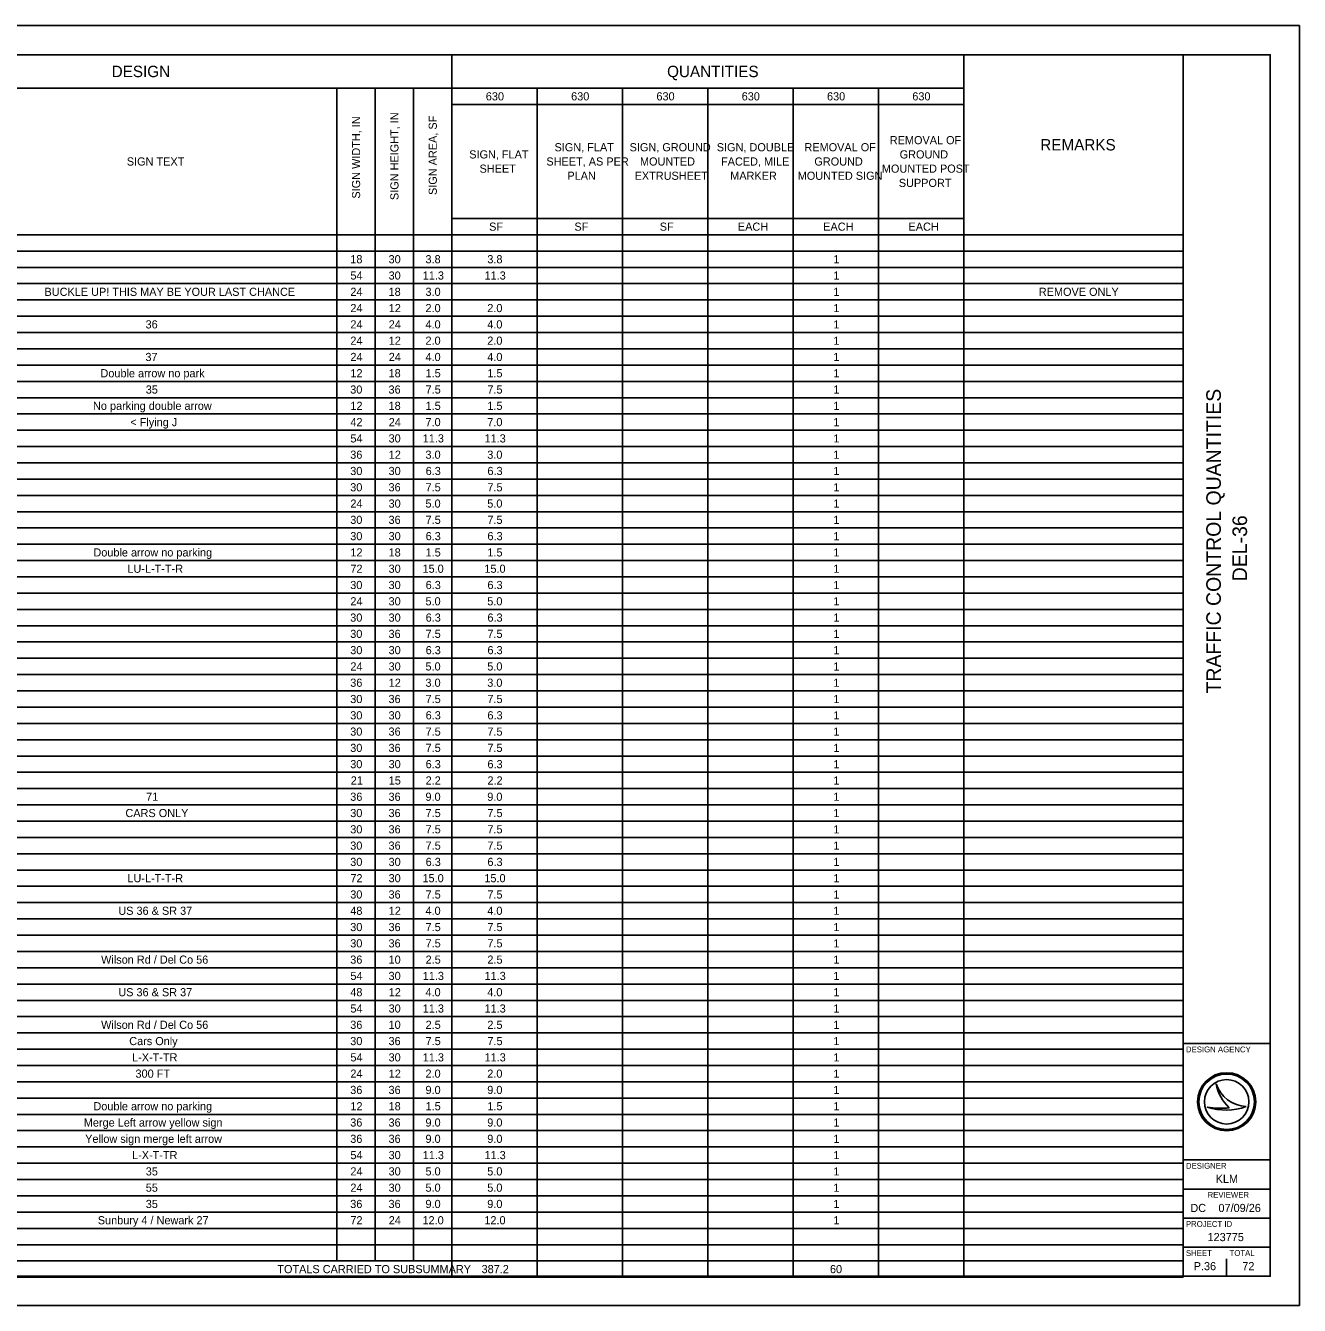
# Model space of a CAD drawing. Extents: x 0 to 34, y 0 to 22.
# Drawn here: x 12.11 to 34, y 0 to 22 of the extents above; entities that cross this region are included whole.
import ezdxf

# ---------------------------------------------------------------- set-up
doc = ezdxf.new("R2010")
doc.units = 0
for name, color, linetype in [('SH_Border', 7, 'Continuous'), ('SH_Cut_Line', 7, 'Continuous'), ('SH_Data', 7, 'Continuous'), ('SH_Text', 7, 'Continuous')]:
    doc.layers.add(name, color=color, linetype=linetype)

msp = doc.modelspace()

# ---------------------------------------------------------------- linework, layer by layer
at = {"layer": 'SH_Border'}
for p, q in [((32, 0.5), (32, 21.5)), ((32, 4.5), (33.5, 4.5)), ((32, 2.5), (33.5, 2.5)), ((32, 2), (33.5, 2)), ((32, 1.5), (33.5, 1.5)), ((32, 1), (33.5, 1))]:
    msp.add_line(p, q, dxfattribs=at)
msp.add_lwpolyline([(1.5, 21.5), (33.5, 21.5), (33.5, 0.5), (1.5, 0.5)], close=True, dxfattribs=at)
at = {"layer": 'SH_Cut_Line'}
msp.add_lwpolyline([(0, 0), (34, 0), (34, 22), (0, 22)], close=True, dxfattribs=at)
at = {"layer": 'SH_Data'}
for p, q in [((1.5, 21.5), (32.004, 21.5)), ((19.436, 21.5), (19.436, 0.484)), ((28.232, 21.5), (28.232, 0.484)), ((32.004, 21.5), (32.004, 0.484)), ((1.5, 20.924), (28.232, 20.924)), ((17.46, 20.924), (17.46, 0.764)), ((18.119, 20.924), (18.119, 0.764)), ((18.778, 20.924), (18.778, 0.764)), ((20.902, 20.924), (20.902, 0.484)), ((22.368, 20.924), (22.368, 0.484)), ((23.834, 20.924), (23.834, 0.484)), ((25.3, 20.924), (25.3, 0.484)), ((26.766, 20.924), (26.766, 0.484)), ((19.436, 20.644), (28.232, 20.644)), ((19.436, 18.684), (28.232, 18.684)), ((1.5, 18.404), (32.004, 18.404)), ((1.5, 18.124), (32.004, 18.124)), ((1.5, 17.844), (32.004, 17.844)), ((1.5, 17.564), (32.004, 17.564)), ((1.5, 17.284), (32.004, 17.284)), ((1.5, 17.004), (32.004, 17.004)), ((1.5, 16.724), (32.004, 16.724)), ((1.5, 16.444), (32.004, 16.444)), ((1.5, 16.164), (32.004, 16.164)), ((1.5, 15.884), (32.004, 15.884)), ((1.5, 15.604), (32.004, 15.604)), ((1.5, 15.324), (32.004, 15.324)), ((1.5, 15.044), (32.004, 15.044)), ((1.5, 14.764), (32.004, 14.764)), ((1.5, 14.484), (32.004, 14.484)), ((1.5, 14.204), (32.004, 14.204)), ((1.5, 13.924), (32.004, 13.924)), ((1.5, 13.644), (32.004, 13.644)), ((1.5, 13.364), (32.004, 13.364)), ((1.5, 13.084), (32.004, 13.084)), ((1.5, 12.804), (32.004, 12.804)), ((1.5, 12.524), (32.004, 12.524)), ((1.5, 12.244), (32.004, 12.244)), ((1.5, 11.964), (32.004, 11.964)), ((1.5, 11.684), (32.004, 11.684)), ((1.5, 11.404), (32.004, 11.404)), ((1.5, 11.124), (32.004, 11.124)), ((1.5, 10.844), (32.004, 10.844)), ((1.5, 10.564), (32.004, 10.564)), ((1.5, 10.284), (32.004, 10.284)), ((1.5, 10.004), (32.004, 10.004)), ((1.5, 9.724), (32.004, 9.724)), ((1.5, 9.444), (32.004, 9.444)), ((1.5, 9.164), (32.004, 9.164)), ((1.5, 8.884), (32.004, 8.884)), ((1.5, 8.604), (32.004, 8.604)), ((1.5, 8.324), (32.004, 8.324)), ((1.5, 8.044), (32.004, 8.044)), ((1.5, 7.764), (32.004, 7.764)), ((1.5, 7.484), (32.004, 7.484)), ((1.5, 7.204), (32.004, 7.204)), ((1.5, 6.924), (32.004, 6.924)), ((1.5, 6.644), (32.004, 6.644)), ((1.5, 6.364), (32.004, 6.364)), ((1.5, 6.084), (32.004, 6.084)), ((1.5, 5.804), (32.004, 5.804)), ((1.5, 5.524), (32.004, 5.524)), ((1.5, 5.244), (32.004, 5.244)), ((1.5, 4.964), (32.004, 4.964)), ((1.5, 4.684), (32.004, 4.684)), ((1.5, 4.404), (32.004, 4.404)), ((1.5, 4.124), (32.004, 4.124)), ((1.5, 3.844), (32.004, 3.844)), ((32.567, 3.81), (32.567, 3.81)), ((1.5, 3.564), (32.004, 3.564)), ((32.417, 3.41), (32.417, 3.41)), ((32.75, 3.5), (32.75, 3.5)), ((33.087, 3.419), (33.087, 3.419)), ((1.5, 3.284), (32.004, 3.284)), ((1.5, 3.004), (32.004, 3.004)), ((1.5, 2.724), (32.004, 2.724)), ((1.5, 2.444), (32.004, 2.444)), ((1.5, 2.164), (32.004, 2.164)), ((1.5, 1.884), (32.004, 1.884)), ((1.5, 1.604), (32.004, 1.604)), ((1.5, 1.324), (32.004, 1.324)), ((1.5, 1.044), (32.004, 1.044)), ((1.5, 0.764), (32.004, 0.764)), ((32.375, 0.675), (32.375, 0.675)), ((32.75, 0.5), (32.75, 0.8)), ((1.5, 0.484), (32.004, 0.484))]:
    msp.add_line(p, q, dxfattribs=at)
for radius in [0.5, 0.477, 0.477, 0.382]:
    msp.add_circle((32.75, 3.5), radius, dxfattribs=at)
for centre, radius, start, end in [((33.116, 3.998), 0.58, 198.9257, 198.9319), ((33.347, 3.97), 0.796, 191.6379, 191.6421), ((33.116, 3.998), 0.58, 198.9319, 267.1657), ((33.347, 3.97), 0.796, 191.6421, 226.0947), ((32.739, 4.37), 1.013, 251.4576, 290.0832), ((32.648, 4.654), 1.266, 259.4964, 259.4995), ((32.739, 4.37), 1.013, 251.4527, 251.4576), ((32.648, 4.654), 1.266, 259.4995, 276.6672)]:
    msp.add_arc(centre, radius, start, end, dxfattribs=at)

# ---------------------------------------------------------------- texts
for s, p in [('TRAFFIC CONTROL QUANTITIES', (32.65, 10.519)), ('DEL-36', (33.1, 12.448))]:
    msp.add_text(s, height=0.25, rotation=90, dxfattribs=at).set_placement(p)
for s, height, p in [('DESIGN AGENCY', 0.1, (32.05, 4.35)), ('DESIGNER', 0.1, (32.05, 2.35)), ('KLM', 0.14, (32.561, 2.105)), ('REVIEWER', 0.1, (32.422, 1.85)), ('DC', 0.14, (32.126, 1.605)), ('07/09/26', 0.14, (32.609, 1.605)), ('PROJECT ID', 0.1, (32.05, 1.35)), ('123775', 0.14, (32.421, 1.105)), ('SHEET', 0.1, (32.05, 0.85)), ('TOTAL', 0.1, (32.8, 0.85)), ('P.36', 0.14, (32.183, 0.605)), ('72', 0.14, (33.019, 0.605))]:
    msp.add_text(s, height=height, dxfattribs=at).set_placement(p)
at = {"layer": 'SH_Text'}
for s, height, p in [('DESIGN', 0.196, (13.589, 21.114)), ('QUANTITIES', 0.196, (23.134, 21.114)), ('630', 0.14, (20.019, 20.714)), ('630', 0.14, (21.485, 20.714)), ('630', 0.14, (22.951, 20.714)), ('630', 0.14, (24.416, 20.714)), ('630', 0.14, (25.882, 20.714)), ('630', 0.14, (27.348, 20.714)), ('REMOVAL OF ', 0.14, (26.961, 19.961)), ('REMARKS', 0.196, (29.547, 19.854)), ('SIGN, FLAT ', 0.14, (19.734, 19.716)), ('SIGN, FLAT ', 0.14, (21.2, 19.839)), ('SIGN, GROUND ', 0.14, (22.49, 19.839)), ('SIGN, DOUBLE ', 0.14, (23.988, 19.839)), ('REMOVAL OF ', 0.14, (25.495, 19.839)), ('GROUND ', 0.14, (27.131, 19.716)), ('SIGN TEXT', 0.14, (13.85, 19.594)), ('SHEET', 0.14, (19.911, 19.471)), ('SHEET, AS PER ', 0.14, (21.06, 19.594)), ('MOUNTED ', 0.14, (22.668, 19.594)), ('FACED, MILE ', 0.14, (24.061, 19.594)), ('GROUND ', 0.14, (25.665, 19.594)), ('MOUNTED POST ', 0.14, (26.825, 19.471)), ('PLAN', 0.14, (21.421, 19.349)), ('EXTRUSHEET', 0.14, (22.576, 19.349)), ('MARKER', 0.14, (24.219, 19.349)), ('MOUNTED SIGN', 0.14, (25.379, 19.349)), ('SUPPORT', 0.14, (27.116, 19.226)), ('SF', 0.14, (20.076, 18.474)), ('SF', 0.14, (21.542, 18.474)), ('SF', 0.14, (23.008, 18.474)), ('EACH', 0.14, (24.351, 18.474)), ('EACH', 0.14, (25.817, 18.474)), ('EACH', 0.14, (27.283, 18.474)), ('18', 0.14, (17.69, 17.914)), ('30', 0.14, (18.348, 17.914)), ('3.8', 0.14, (18.982, 17.914)), ('3.8', 0.14, (20.045, 17.914)), ('1', 0.14, (25.992, 17.914)), ('54', 0.14, (17.692, 17.634)), ('30', 0.14, (18.348, 17.634)), ('11.3', 0.14, (18.935, 17.634)), ('11.3', 0.14, (19.997, 17.634)), ('1', 0.14, (25.992, 17.634)), ('BUCKLE UP! THIS MAY BE YOUR LAST CHANCE', 0.14, (12.435, 17.354)), ('24', 0.14, (17.692, 17.354)), ('18', 0.14, (18.348, 17.354)), ('3.0', 0.14, (18.982, 17.354)), ('1', 0.14, (25.992, 17.354)), ('REMOVE ONLY', 0.14, (29.522, 17.354)), ('24', 0.14, (17.692, 17.074)), ('12', 0.14, (18.351, 17.074)), ('2.0', 0.14, (18.982, 17.074)), ('2.0', 0.14, (20.044, 17.074)), ('1', 0.14, (25.992, 17.074)), ('36', 0.14, (14.172, 16.794)), ('24', 0.14, (17.692, 16.794)), ('24', 0.14, (18.351, 16.794)), ('4.0', 0.14, (18.982, 16.794)), ('4.0', 0.14, (20.044, 16.794)), ('1', 0.14, (25.992, 16.794)), ('24', 0.14, (17.692, 16.514)), ('12', 0.14, (18.351, 16.514)), ('2.0', 0.14, (18.982, 16.514)), ('2.0', 0.14, (20.044, 16.514)), ('1', 0.14, (25.992, 16.514)), ('37', 0.14, (14.169, 16.234)), ('24', 0.14, (17.692, 16.234)), ('24', 0.14, (18.351, 16.234)), ('4.0', 0.14, (18.982, 16.234)), ('4.0', 0.14, (20.044, 16.234)), ('1', 0.14, (25.992, 16.234)), ('Double arrow no park', 0.14, (13.397, 15.954)), ('12', 0.14, (17.692, 15.954)), ('18', 0.14, (18.348, 15.954)), ('1.5', 0.14, (18.984, 15.954)), ('1.5', 0.14, (20.046, 15.954)), ('1', 0.14, (25.992, 15.954)), ('35', 0.14, (14.175, 15.674)), ('30', 0.14, (17.689, 15.674)), ('36', 0.14, (18.347, 15.674)), ('7.5', 0.14, (18.984, 15.674)), ('7.5', 0.14, (20.046, 15.674)), ('1', 0.14, (25.992, 15.674)), ('No parking double arrow', 0.14, (13.269, 15.394)), ('12', 0.14, (17.692, 15.394)), ('18', 0.14, (18.348, 15.394)), ('1.5', 0.14, (18.984, 15.394)), ('1.5', 0.14, (20.046, 15.394)), ('1', 0.14, (25.992, 15.394)), ('< Flying J', 0.14, (13.91, 15.114)), ('42', 0.14, (17.692, 15.114)), ('24', 0.14, (18.351, 15.114)), ('7.0', 0.14, (18.982, 15.114)), ('7.0', 0.14, (20.044, 15.114)), ('1', 0.14, (25.992, 15.114)), ('54', 0.14, (17.692, 14.834)), ('30', 0.14, (18.348, 14.834)), ('11.3', 0.14, (18.935, 14.834)), ('11.3', 0.14, (19.997, 14.834)), ('1', 0.14, (25.992, 14.834)), ('36', 0.14, (17.689, 14.554)), ('12', 0.14, (18.351, 14.554)), ('3.0', 0.14, (18.982, 14.554)), ('3.0', 0.14, (20.044, 14.554)), ('1', 0.14, (25.992, 14.554)), ('30', 0.14, (17.689, 14.274)), ('30', 0.14, (18.348, 14.274)), ('6.3', 0.14, (18.985, 14.274)), ('6.3', 0.14, (20.047, 14.274)), ('1', 0.14, (25.992, 14.274)), ('30', 0.14, (17.689, 13.994)), ('36', 0.14, (18.347, 13.994)), ('7.5', 0.14, (18.984, 13.994)), ('7.5', 0.14, (20.046, 13.994)), ('1', 0.14, (25.992, 13.994)), ('24', 0.14, (17.692, 13.714)), ('30', 0.14, (18.348, 13.714)), ('5.0', 0.14, (18.982, 13.714)), ('5.0', 0.14, (20.044, 13.714)), ('1', 0.14, (25.992, 13.714)), ('30', 0.14, (17.689, 13.434)), ('36', 0.14, (18.347, 13.434)), ('7.5', 0.14, (18.984, 13.434)), ('7.5', 0.14, (20.046, 13.434)), ('1', 0.14, (25.992, 13.434)), ('30', 0.14, (17.689, 13.154)), ('30', 0.14, (18.348, 13.154)), ('6.3', 0.14, (18.985, 13.154)), ('6.3', 0.14, (20.047, 13.154)), ('1', 0.14, (25.992, 13.154)), ('Double arrow no parking', 0.14, (13.276, 12.874)), ('12', 0.14, (17.692, 12.874)), ('18', 0.14, (18.348, 12.874)), ('1.5', 0.14, (18.984, 12.874)), ('1.5', 0.14, (20.046, 12.874)), ('1', 0.14, (25.992, 12.874)), ('LU-L-T-T-R', 0.14, (13.86, 12.594)), ('72', 0.14, (17.692, 12.594)), ('30', 0.14, (18.348, 12.594)), ('15.0', 0.14, (18.931, 12.594)), ('15.0', 0.14, (19.994, 12.594)), ('1', 0.14, (25.992, 12.594)), ('30', 0.14, (17.689, 12.314)), ('30', 0.14, (18.348, 12.314)), ('6.3', 0.14, (18.985, 12.314)), ('6.3', 0.14, (20.047, 12.314)), ('1', 0.14, (25.992, 12.314)), ('24', 0.14, (17.692, 12.034)), ('30', 0.14, (18.348, 12.034)), ('5.0', 0.14, (18.982, 12.034)), ('5.0', 0.14, (20.044, 12.034)), ('1', 0.14, (25.992, 12.034)), ('30', 0.14, (17.689, 11.754)), ('30', 0.14, (18.348, 11.754)), ('6.3', 0.14, (18.985, 11.754)), ('6.3', 0.14, (20.047, 11.754)), ('1', 0.14, (25.992, 11.754)), ('30', 0.14, (17.689, 11.474)), ('36', 0.14, (18.347, 11.474)), ('7.5', 0.14, (18.984, 11.474)), ('7.5', 0.14, (20.046, 11.474)), ('1', 0.14, (25.992, 11.474)), ('30', 0.14, (17.689, 11.194)), ('30', 0.14, (18.348, 11.194)), ('6.3', 0.14, (18.985, 11.194)), ('6.3', 0.14, (20.047, 11.194)), ('1', 0.14, (25.992, 11.194)), ('24', 0.14, (17.692, 10.914)), ('30', 0.14, (18.348, 10.914)), ('5.0', 0.14, (18.982, 10.914)), ('5.0', 0.14, (20.044, 10.914)), ('1', 0.14, (25.992, 10.914)), ('36', 0.14, (17.689, 10.634)), ('12', 0.14, (18.351, 10.634)), ('3.0', 0.14, (18.982, 10.634)), ('3.0', 0.14, (20.044, 10.634)), ('1', 0.14, (25.992, 10.634)), ('30', 0.14, (17.689, 10.354)), ('36', 0.14, (18.347, 10.354)), ('7.5', 0.14, (18.984, 10.354)), ('7.5', 0.14, (20.046, 10.354)), ('1', 0.14, (25.992, 10.354)), ('30', 0.14, (17.689, 10.074)), ('30', 0.14, (18.348, 10.074)), ('6.3', 0.14, (18.985, 10.074)), ('6.3', 0.14, (20.047, 10.074)), ('1', 0.14, (25.992, 10.074)), ('30', 0.14, (17.689, 9.794)), ('36', 0.14, (18.347, 9.794)), ('7.5', 0.14, (18.984, 9.794)), ('7.5', 0.14, (20.046, 9.794)), ('1', 0.14, (25.992, 9.794)), ('30', 0.14, (17.689, 9.514)), ('36', 0.14, (18.347, 9.514)), ('7.5', 0.14, (18.984, 9.514)), ('7.5', 0.14, (20.046, 9.514)), ('1', 0.14, (25.992, 9.514)), ('30', 0.14, (17.689, 9.234)), ('30', 0.14, (18.348, 9.234)), ('6.3', 0.14, (18.985, 9.234)), ('6.3', 0.14, (20.047, 9.234)), ('1', 0.14, (25.992, 9.234)), ('21', 0.14, (17.698, 8.954)), ('15', 0.14, (18.35, 8.954)), ('2.2', 0.14, (18.985, 8.954)), ('2.2', 0.14, (20.047, 8.954)), ('1', 0.14, (25.992, 8.954)), ('71', 0.14, (14.181, 8.674)), ('36', 0.14, (17.689, 8.674)), ('36', 0.14, (18.347, 8.674)), ('9.0', 0.14, (18.982, 8.674)), ('9.0', 0.14, (20.044, 8.674)), ('1', 0.14, (25.992, 8.674)), ('CARS ONLY', 0.14, (13.826, 8.394)), ('30', 0.14, (17.689, 8.394)), ('36', 0.14, (18.347, 8.394)), ('7.5', 0.14, (18.984, 8.394)), ('7.5', 0.14, (20.046, 8.394)), ('1', 0.14, (25.992, 8.394)), ('30', 0.14, (17.689, 8.114)), ('36', 0.14, (18.347, 8.114)), ('7.5', 0.14, (18.984, 8.114)), ('7.5', 0.14, (20.046, 8.114)), ('1', 0.14, (25.992, 8.114)), ('30', 0.14, (17.689, 7.834)), ('36', 0.14, (18.347, 7.834)), ('7.5', 0.14, (18.984, 7.834)), ('7.5', 0.14, (20.046, 7.834)), ('1', 0.14, (25.992, 7.834)), ('30', 0.14, (17.689, 7.554)), ('30', 0.14, (18.348, 7.554)), ('6.3', 0.14, (18.985, 7.554)), ('6.3', 0.14, (20.047, 7.554)), ('1', 0.14, (25.992, 7.554)), ('LU-L-T-T-R', 0.14, (13.86, 7.274)), ('72', 0.14, (17.692, 7.274)), ('30', 0.14, (18.348, 7.274)), ('15.0', 0.14, (18.931, 7.274)), ('15.0', 0.14, (19.994, 7.274)), ('1', 0.14, (25.992, 7.274)), ('30', 0.14, (17.689, 6.994)), ('36', 0.14, (18.347, 6.994)), ('7.5', 0.14, (18.984, 6.994)), ('7.5', 0.14, (20.046, 6.994)), ('1', 0.14, (25.992, 6.994)), ('US 36 & SR 37', 0.14, (13.704, 6.714)), ('48', 0.14, (17.69, 6.714)), ('12', 0.14, (18.351, 6.714)), ('4.0', 0.14, (18.982, 6.714)), ('4.0', 0.14, (20.044, 6.714)), ('1', 0.14, (25.992, 6.714)), ('30', 0.14, (17.689, 6.434)), ('36', 0.14, (18.347, 6.434)), ('7.5', 0.14, (18.984, 6.434)), ('7.5', 0.14, (20.046, 6.434)), ('1', 0.14, (25.992, 6.434)), ('30', 0.14, (17.689, 6.154)), ('36', 0.14, (18.347, 6.154)), ('7.5', 0.14, (18.984, 6.154)), ('7.5', 0.14, (20.046, 6.154)), ('1', 0.14, (25.992, 6.154)), ('Wilson Rd / Del Co 56', 0.14, (13.408, 5.874)), ('36', 0.14, (17.689, 5.874)), ('10', 0.14, (18.348, 5.874)), ('2.5', 0.14, (18.984, 5.874)), ('2.5', 0.14, (20.046, 5.874)), ('1', 0.14, (25.992, 5.874)), ('54', 0.14, (17.692, 5.594)), ('30', 0.14, (18.348, 5.594)), ('11.3', 0.14, (18.935, 5.594)), ('11.3', 0.14, (19.997, 5.594)), ('1', 0.14, (25.992, 5.594)), ('US 36 & SR 37', 0.14, (13.704, 5.314)), ('48', 0.14, (17.69, 5.314)), ('12', 0.14, (18.351, 5.314)), ('4.0', 0.14, (18.982, 5.314)), ('4.0', 0.14, (20.044, 5.314)), ('1', 0.14, (25.992, 5.314)), ('54', 0.14, (17.692, 5.034)), ('30', 0.14, (18.348, 5.034)), ('11.3', 0.14, (18.935, 5.034)), ('11.3', 0.14, (19.997, 5.034)), ('1', 0.14, (25.992, 5.034)), ('Wilson Rd / Del Co 56', 0.14, (13.408, 4.754)), ('36', 0.14, (17.689, 4.754)), ('10', 0.14, (18.348, 4.754)), ('2.5', 0.14, (18.984, 4.754)), ('2.5', 0.14, (20.046, 4.754)), ('1', 0.14, (25.992, 4.754)), ('Cars Only', 0.14, (13.891, 4.474)), ('30', 0.14, (17.689, 4.474)), ('36', 0.14, (18.347, 4.474)), ('7.5', 0.14, (18.984, 4.474)), ('7.5', 0.14, (20.046, 4.474)), ('1', 0.14, (25.992, 4.474)), ('L-X-T-TR', 0.14, (13.94, 4.194)), ('54', 0.14, (17.692, 4.194)), ('30', 0.14, (18.348, 4.194)), ('11.3', 0.14, (18.935, 4.194)), ('11.3', 0.14, (19.997, 4.194)), ('1', 0.14, (25.992, 4.194)), ('300 FT', 0.14, (13.999, 3.914)), ('24', 0.14, (17.692, 3.914)), ('12', 0.14, (18.351, 3.914)), ('2.0', 0.14, (18.982, 3.914)), ('2.0', 0.14, (20.044, 3.914)), ('1', 0.14, (25.992, 3.914)), ('36', 0.14, (17.689, 3.634)), ('36', 0.14, (18.347, 3.634)), ('9.0', 0.14, (18.982, 3.634)), ('9.0', 0.14, (20.044, 3.634)), ('1', 0.14, (25.992, 3.634)), ('Double arrow no parking', 0.14, (13.276, 3.354)), ('12', 0.14, (17.692, 3.354)), ('18', 0.14, (18.348, 3.354)), ('1.5', 0.14, (18.984, 3.354)), ('1.5', 0.14, (20.046, 3.354)), ('1', 0.14, (25.992, 3.354)), ('Merge Left arrow yellow sign', 0.14, (13.111, 3.074)), ('36', 0.14, (17.689, 3.074)), ('36', 0.14, (18.347, 3.074)), ('9.0', 0.14, (18.982, 3.074)), ('9.0', 0.14, (20.044, 3.074)), ('1', 0.14, (25.992, 3.074)), ('Yellow sign merge left arrow', 0.14, (13.134, 2.794)), ('36', 0.14, (17.689, 2.794)), ('36', 0.14, (18.347, 2.794)), ('9.0', 0.14, (18.982, 2.794)), ('9.0', 0.14, (20.044, 2.794)), ('1', 0.14, (25.992, 2.794)), ('L-X-T-TR', 0.14, (13.94, 2.514)), ('54', 0.14, (17.692, 2.514)), ('30', 0.14, (18.348, 2.514)), ('11.3', 0.14, (18.935, 2.514)), ('11.3', 0.14, (19.997, 2.514)), ('1', 0.14, (25.992, 2.514)), ('35', 0.14, (14.175, 2.234)), ('24', 0.14, (17.692, 2.234)), ('30', 0.14, (18.348, 2.234)), ('5.0', 0.14, (18.982, 2.234)), ('5.0', 0.14, (20.044, 2.234)), ('1', 0.14, (25.992, 2.234)), ('55', 0.14, (14.175, 1.954)), ('24', 0.14, (17.692, 1.954)), ('30', 0.14, (18.348, 1.954)), ('5.0', 0.14, (18.982, 1.954)), ('5.0', 0.14, (20.044, 1.954)), ('1', 0.14, (25.992, 1.954)), ('35', 0.14, (14.175, 1.674)), ('36', 0.14, (17.689, 1.674)), ('36', 0.14, (18.347, 1.674)), ('9.0', 0.14, (18.982, 1.674)), ('9.0', 0.14, (20.044, 1.674)), ('1', 0.14, (25.992, 1.674)), ('Sunbury 4 / Newark 27', 0.14, (13.351, 1.394)), ('72', 0.14, (17.692, 1.394)), ('24', 0.14, (18.351, 1.394)), ('12.0', 0.14, (18.931, 1.394)), ('12.0', 0.14, (19.994, 1.394)), ('1', 0.14, (25.992, 1.394)), ('TOTALS CARRIED TO SUBSUMMARY', 0.14, (16.436, 0.554)), ('387.2', 0.14, (19.946, 0.554)), ('60', 0.14, (25.933, 0.554))]:
    msp.add_text(s, height=height, dxfattribs=at).set_placement(p)
for s, p in [('SIGN HEIGHT, IN', (18.518, 19.001)), ('SIGN WIDTH, IN', (17.859, 19.026)), ('SIGN AREA, SF', (19.177, 19.088))]:
    msp.add_text(s, height=0.14, rotation=90, dxfattribs=at).set_placement(p)

doc.saveas('drawing.dxf')
